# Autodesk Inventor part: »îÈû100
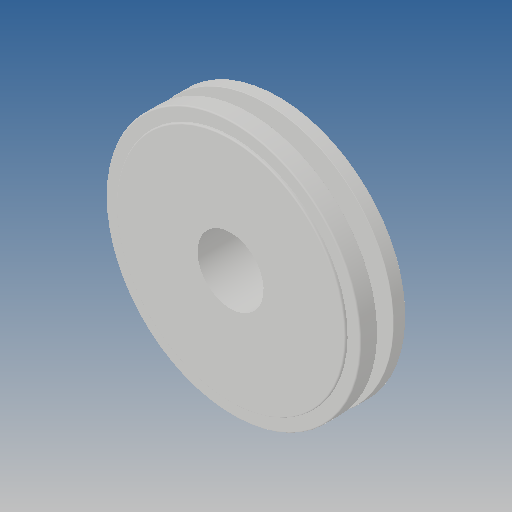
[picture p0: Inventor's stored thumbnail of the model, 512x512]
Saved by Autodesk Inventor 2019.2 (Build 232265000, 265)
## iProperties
Created: 2013-07
Part Number: »îÈû100
Material: Ogólny
Document SubType Name: Modeling
Designer: CADENGINEERING4
Density: 1 g/cm^3
Appearance: Domyślna
Author: CADENGINEERING4
Revision Number: ÈÎºÎ
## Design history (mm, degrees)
feature "CALC100-»îÈû.bak-1-solid1"
node "Bryła1"
